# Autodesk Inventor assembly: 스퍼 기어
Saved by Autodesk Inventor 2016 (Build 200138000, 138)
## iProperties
Created: 2018-09
Part Number: 스퍼 기어
Document SubType Name: Assembly
Designer: MYS
Categories: <?xml version="1.0" encoding="UTF-16"?> <MemberInstance><Categories><FamilyTemplate/><ParamToTemplateMap><ParamToTemplate><ParamToTemplate CategoryParameter="//
ClientObjectVersion: 1
Author: MYS
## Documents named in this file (1)
- C:\Users\MYS\Desktop\답안\2단 스퍼기어\디자인 액셀러레이터\스퍼 기어1.iam
